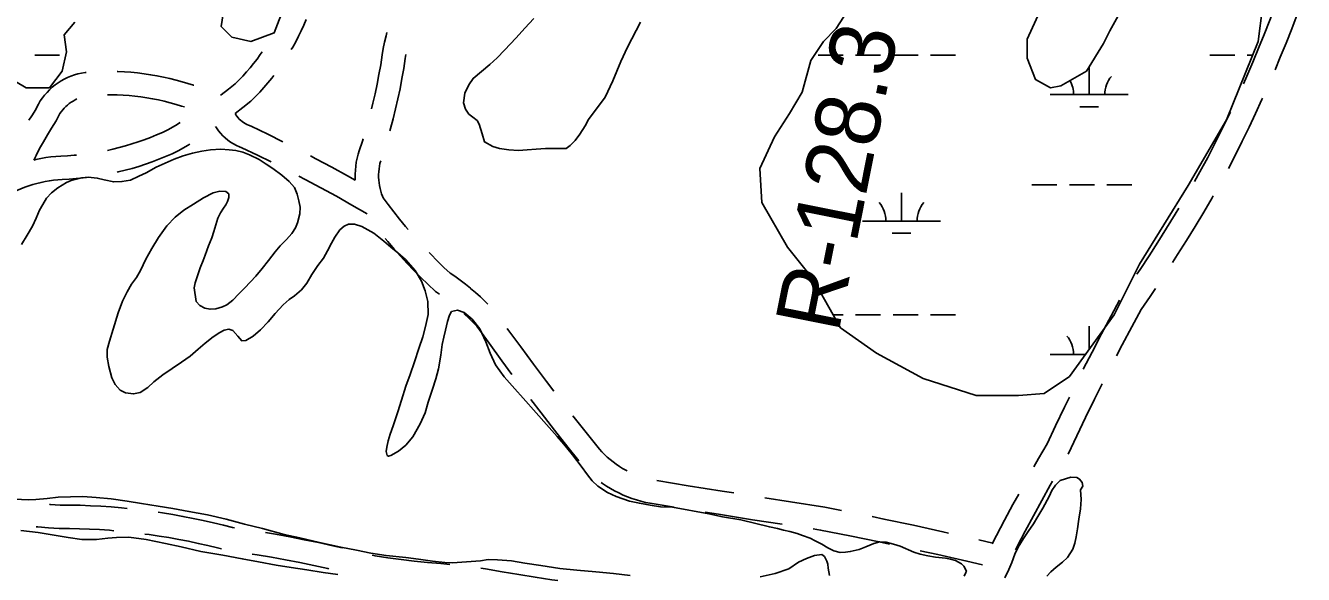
# Model space of a CAD drawing. Extents: x 3535183 to 3573198, y 534952 to 560562.
# Drawn here: x 3560733 to 3562370, y 548151 to 548854 of the extents above; entities that cross this region are included whole.
import ezdxf

# ---------------------------------------------------------------- set-up
doc = ezdxf.new("R2010")
doc.units = 0
for name, color, linetype in [('V-RIVR-RANG-IDEN', 7, 'Continuous'), ('V-ROAD-CNTR', 7, 'Continuous'), ('V-TOPO-SHOR', 7, 'Continuous'), ('V-WETL-SWMP', 7, 'Continuous')]:
    doc.layers.add(name, color=color, linetype=linetype)

msp = doc.modelspace()

# ---------------------------------------------------------------- linework, layer by layer
at = {"layer": 'V-ROAD-CNTR'}
msp.add_line((3561954.5, 548194.8), (3561972.4, 548190.7), dxfattribs=at)
for points in [[(3562370.2, 548890.2), (3562369.2, 548886.7), (3562362.2, 548867.9), (3562355.2, 548849.5), (3562348, 548831.2), (3562340.6, 548813), (3562333.9, 548797.1)], [(3561092.4, 548861.5), (3561089.4, 548854.3), (3561086.1, 548847.1), (3561082.7, 548839.9), (3561079, 548832.9), (3561075.2, 548825.9), (3561073.4, 548822.8)], [(3562331.5, 548871.6), (3562327.2, 548860.4), (3562320.1, 548842.4), (3562312.8, 548824.5), (3562305.3, 548806.7), (3562297.7, 548788.9), (3562293.3, 548779.2)], [(3561196, 548844.9), (3561194.8, 548840.5), (3561192.9, 548832.4), (3561191.3, 548824.3), (3561189.8, 548816.2), (3561187.9, 548803.5), (3561185.7, 548791), (3561183.4, 548778.7), (3561180.8, 548766.3), (3561177.9, 548754.1), (3561176.2, 548746.9)], [(3561036, 548819.8), (3561033.7, 548816.6), (3561029.5, 548810.8), (3561025.1, 548805.1), (3561020.6, 548799.6), (3561015.9, 548794.2), (3561011.1, 548788.9), (3561006.2, 548783.8), (3561001.5, 548779.2), (3560992.8, 548772.3), (3560983.5, 548765.1), (3560982.7, 548764.5)], [(3561220.3, 548816.4), (3561219.4, 548811.3), (3561217.5, 548798.6), (3561215.2, 548785.7), (3561212.8, 548772.8), (3561210.1, 548759.9), (3561207.1, 548747.1), (3561204, 548734.3), (3561200.6, 548721.6), (3561199.7, 548718.6)], [(3560810.4, 548793.5), (3560809.2, 548793.4), (3560804.5, 548792.6), (3560800, 548791.6), (3560795.5, 548790.4), (3560791.1, 548788.9), (3560786.7, 548787.1), (3560782.5, 548785), (3560778.5, 548782.8), (3560774.5, 548780.3), (3560770.7, 548777.6), (3560767.1, 548774.6), (3560763.6, 548771.5), (3560760.4, 548768.1), (3560757.3, 548764.6), (3560754.4, 548760.9), (3560751.8, 548757.1), (3560749.4, 548753.1), (3560747.2, 548749), (3560745.9, 548746.1), (3560740.8, 548738.1), (3560737.3, 548732.4)], [(3560948.5, 548777.1), (3560948, 548777.3), (3560940.7, 548779.5), (3560933.7, 548781.4), (3560925.9, 548783.6), (3560917.8, 548785.7), (3560909.6, 548787.6), (3560901.3, 548789.3), (3560893, 548790.7), (3560884.7, 548792), (3560876.4, 548793), (3560868, 548793.8), (3560859.6, 548794.4), (3560851.2, 548794.8), (3560850.4, 548794.8)], [(3561051.1, 548789.7), (3561048.6, 548786.4), (3561043.5, 548780.3), (3561038.4, 548774.3), (3561033, 548768.4), (3561027.5, 548762.7), (3561021.4, 548756.7), (3561011.3, 548748.6), (3561001.6, 548741.2), (3561001.3, 548740.9)], [(3560936.5, 548749.4), (3560932.5, 548750.6), (3560925.7, 548752.5), (3560918, 548754.6), (3560910.6, 548756.6), (3560903.2, 548758.3), (3560895.7, 548759.8), (3560888.2, 548761.1), (3560880.7, 548762.2), (3560873.1, 548763.2), (3560865.5, 548763.9), (3560857.9, 548764.4), (3560850.3, 548764.8), (3560842.7, 548764.9), (3560838.1, 548764.9)], [(3562317.8, 548760.5), (3562317.1, 548758.9), (3562308.9, 548741), (3562300.5, 548723.3), (3562291.9, 548705.6), (3562283.1, 548688), (3562274.1, 548670.5)], [(3560798.8, 548759.6), (3560796.3, 548758.4), (3560793.8, 548757), (3560791.3, 548755.4), (3560788.9, 548753.7), (3560786.6, 548751.8), (3560784.5, 548749.9), (3560782.4, 548747.8), (3560780.5, 548745.6), (3560778.7, 548743.3), (3560777, 548740.8), (3560775.5, 548738.3), (3560774.1, 548735.7), (3560772.3, 548731.7), (3560766.2, 548722.2), (3560760.9, 548713.6), (3560755.8, 548704.9), (3560750.9, 548696.1), (3560746.3, 548687.2), (3560743.4, 548681.4)], [(3560930.8, 548729.3), (3560925, 548725.8), (3560915.4, 548720.1), (3560908.3, 548716.8), (3560900.6, 548713.5), (3560892.8, 548710.3), (3560885, 548707.3), (3560877.1, 548704.6), (3560869.1, 548702), (3560861.1, 548699.6), (3560853, 548697.4), (3560844.8, 548695.4), (3560837.8, 548693.8)], [(3561062.6, 548704.9), (3561043.2, 548714.5), (3561021.8, 548724.8), (3561018.5, 548726.1), (3561016.4, 548727), (3561014.3, 548728.2), (3561012.3, 548729.4), (3561010.4, 548730.8), (3561008.5, 548732.3), (3561006.8, 548733.9), (3561005.2, 548735.6), (3561003.7, 548737.4), (3561002.3, 548739.3), (3561001.3, 548740.9)], [(3562276.6, 548742.9), (3562273.4, 548736.2), (3562265, 548718.8), (3562256.4, 548701.6), (3562247.6, 548684.5), (3562237.5, 548666.3), (3562230.6, 548654.1)], [(3561047.6, 548678.9), (3561030, 548687.6), (3561010, 548697.2), (3561007, 548698.4), (3561003.1, 548700.1), (3560999.3, 548702.2), (3560995.6, 548704.4), (3560992.1, 548706.9), (3560988.8, 548709.7), (3560985.7, 548712.6), (3560982.7, 548715.7), (3560980, 548719), (3560977.4, 548722.5), (3560976.2, 548724.4)], [(3560943.3, 548701.7), (3560940.4, 548700), (3560929.3, 548693.5), (3560920.6, 548689.4), (3560912.2, 548685.8), (3560903.8, 548682.4), (3560895.3, 548679.2), (3560886.7, 548676.1), (3560878, 548673.3), (3560869.3, 548670.7), (3560860.5, 548668.3), (3560851.7, 548666.2), (3560850.4, 548665.9)], [(3561165.4, 548708.4), (3561164.5, 548705.5), (3561160.5, 548693.3), (3561159, 548688.7), (3561157.8, 548683.8), (3561156.7, 548678.7), (3561156, 548673.7), (3561155.5, 548668.6), (3561155.2, 548663.5), (3561155.2, 548658.4), (3561155.4, 548655.6)], [(3560798.3, 548687.8), (3560795.2, 548687.5), (3560786.8, 548686.8), (3560778.2, 548686.4), (3560771.8, 548686), (3560765.4, 548685.4), (3560759, 548684.5), (3560752.6, 548683.4), (3560746.2, 548682.1), (3560743.4, 548681.4)], [(3561155.4, 548655.6), (3561145.6, 548661.1), (3561125.4, 548672.2), (3561105, 548683.1), (3561098.2, 548686.7)], [(3561187.9, 548680.4), (3561187, 548677), (3561186.3, 548673.5), (3561185.8, 548670), (3561185.4, 548666.4), (3561185.2, 548662.8), (3561185.2, 548659.3), (3561185.4, 548655.7), (3561185.8, 548652.1), (3561186.4, 548648.6), (3561187.1, 548645.1), (3561188, 548641.6), (3561189.1, 548638.2), (3561190.4, 548634.9), (3561191.3, 548632.8), (3561197.5, 548624.4), (3561204.8, 548614.9), (3561212.2, 548605.5), (3561219.8, 548596.3), (3561223.1, 548592.5)], [(3560811, 548659), (3560806.8, 548658.5), (3560797.8, 548657.6), (3560788.7, 548656.9), (3560779.9, 548656.5), (3560774.3, 548656.1), (3560768.9, 548655.6), (3560763.5, 548654.8), (3560758.1, 548653.9), (3560752.8, 548652.8), (3560747.5, 548651.5), (3560742.2, 548650.1), (3560737, 548648.4), (3560731.9, 548646.6), (3560726.8, 548644.7), (3560721.8, 548642.5), (3560716.8, 548640.2), (3560714, 548638.7)], [(3561170.7, 548612.3), (3561150.9, 548623.7), (3561131.1, 548634.9), (3561111.1, 548645.8), (3561091, 548656.6), (3561083.2, 548660.6)], [(3562254.6, 548635.6), (3562253.1, 548633.1), (3562242.4, 548614.7), (3562231.5, 548596.4), (3562220.3, 548578.2), (3562209, 548560.2), (3562202.6, 548550.2)], [(3562210.4, 548619.6), (3562205.8, 548611.9), (3562194.8, 548594), (3562183.7, 548576.2), (3562172.4, 548558.5), (3562160.8, 548541), (3562156.9, 548535.1)], [(3561193.6, 548581), (3561196.9, 548577), (3561205, 548567.4), (3561213.3, 548558.1), (3561221.8, 548548.9), (3561230.5, 548539.8), (3561239.3, 548530.9), (3561248.3, 548522.2), (3561258.2, 548512.9), (3561263.2, 548509.5)], [(3561249.9, 548562.9), (3561252, 548560.7), (3561260.4, 548552.2), (3561269, 548543.9), (3561277, 548536.4), (3561282.8, 548532.5), (3561289.7, 548527.6), (3561296.4, 548522.5), (3561302.9, 548517.3)], [(3561303.2, 548517), (3561309.5, 548511.7), (3561315.8, 548506.1), (3561321.9, 548500.3), (3561325.3, 548496.9)], [(3562180.7, 548516.8), (3562173.9, 548506.7), (3562162.4, 548489.9), (3562150.3, 548467.6), (3562138, 548444.6), (3562130.6, 548430.4)], [(3562134.7, 548501.8), (3562123.9, 548481.8), (3562111.5, 548458.6), (3562099.3, 548435.3), (3562088.1, 548413.4)], [(3561294.3, 548485), (3561295.4, 548484), (3561301, 548478.8), (3561306.4, 548473.4), (3561311.1, 548468.4), (3561326.7, 548446.7), (3561343.2, 548424.2), (3561356.1, 548406.8)], [(3561350.1, 548465.6), (3561351, 548464.3), (3561367.3, 548442), (3561383.8, 548419.8), (3561400.4, 548397.8), (3561409.9, 548385.4)], [(3562112.4, 548394.8), (3562102.5, 548375.1), (3562091.1, 548351.7), (3562079.9, 548328.2), (3562068.9, 548304.7)], [(3561380.2, 548374.8), (3561393.4, 548357.5), (3561410.5, 548335.5), (3561427.8, 548313.7), (3561441.8, 548296.1)], [(3562070.3, 548377.5), (3562064.1, 548364.8), (3562052.7, 548341), (3562041.9, 548317.9), (3562030.9, 548299.1), (3562024.9, 548288.5)], [(3561434.3, 548353.8), (3561451.3, 548332.3), (3561468.3, 548311.1), (3561471.4, 548307.6), (3561474.8, 548304.1), (3561478.3, 548300.8), (3561482, 548297.6), (3561485.8, 548294.6), (3561489.7, 548291.7), (3561493.7, 548289), (3561497.8, 548286.4), (3561502, 548284), (3561503.8, 548283.1)], [(3561541.6, 548270.7), (3561581.9, 548264.2), (3561625.5, 548257.2), (3561640.3, 548254.9)], [(3562048.9, 548270), (3562045.9, 548264.8), (3562035, 548245.4), (3562024.3, 548225.8), (3562013.8, 548206.2), (3562003.5, 548186.5), (3562001.2, 548182.1)], [(3561470.6, 548268.5), (3561472.3, 548267.2), (3561477.3, 548263.8), (3561482.5, 548260.6), (3561487.7, 548257.6), (3561493.1, 548254.9), (3561498.6, 548252.3), (3561504.1, 548250), (3561509.8, 548247.9), (3561515.5, 548246), (3561521.4, 548244.3), (3561527.2, 548242.9), (3561533.1, 548241.7), (3561564.1, 548236.7)], [(3562005.4, 548253.6), (3561998, 548240.1), (3561987.3, 548220.3), (3561976.9, 548200.3), (3561971.4, 548189.8)], [(3560763.4, 548240.4), (3560764.4, 548240.3), (3560777.1, 548239.5), (3560789.8, 548239.4), (3560803, 548239.1), (3560816.3, 548238.6), (3560829.5, 548237.9), (3560842.7, 548237), (3560855.9, 548235.9), (3560863.2, 548235.2)], [(3561679.9, 548248.7), (3561712.8, 548243.6), (3561756.8, 548236.9), (3561778.5, 548232.6)], [(3560902.9, 548230.2), (3560908.5, 548229.4), (3560921.6, 548227.3), (3560934.6, 548224.9), (3560947.6, 548222.4), (3560960.6, 548219.6), (3560973.5, 548216.7), (3560986.4, 548213.6), (3560998.2, 548210.5), (3561000.8, 548210.1)], [(3561603.6, 548230.3), (3561620.8, 548227.6), (3561664.5, 548220.7), (3561702.4, 548214.8)], [(3561817.7, 548224.6), (3561832.7, 548221.5), (3561870.5, 548213.5), (3561908.2, 548205.3), (3561915.5, 548203.6)], [(3560746.3, 548211.7), (3560748.6, 548211.5), (3560762.1, 548210.4), (3560776, 548209.5), (3560789.3, 548209.4), (3560802.1, 548209.1), (3560814.9, 548208.6), (3560827.7, 548208), (3560840.4, 548207.1), (3560846.1, 548206.6)], [(3561040.3, 548204.1), (3561053.1, 548202), (3561071.6, 548198.7), (3561090, 548195.1), (3561108.4, 548191.4), (3561126.8, 548187.4), (3561138.4, 548184.7)], [(3561742, 548208.8), (3561751.6, 548207.4), (3561789, 548199.9), (3561826.6, 548192.2), (3561840, 548189.3)], [(3560885.9, 548202.3), (3560891.2, 548201.6), (3560903.9, 548199.7), (3560916.5, 548197.7), (3560929.1, 548195.4), (3560941.6, 548193), (3560954.1, 548190.3), (3560966.6, 548187.5), (3560979, 548184.5), (3560984, 548183.2)], [(3561023.4, 548176.5), (3561029.8, 548175.5), (3561047.9, 548172.5), (3561066.1, 548169.2), (3561084.2, 548165.7), (3561102.2, 548162), (3561120.2, 548158.1), (3561121.6, 548157.8)], [(3561177.2, 548175.1), (3561180.7, 548174.2), (3561197, 548171.9), (3561214, 548169.7), (3561231, 548167.7), (3561248, 548165.9), (3561265.1, 548164.4), (3561276.5, 548163.5)], [(3561879.1, 548180.9), (3561901.7, 548176), (3561939.1, 548167.6), (3561958.9, 548163)], [(3561316.2, 548158.8), (3561322.4, 548157.6), (3561343.6, 548153.8), (3561364.8, 548150.3), (3561386, 548146.9), (3561407.3, 548143.7), (3561414.8, 548142.7)]]:
    msp.add_lwpolyline(points, dxfattribs=at)
at = {"layer": 'V-TOPO-SHOR'}
for points in [[(3561520.7, 548858.1), (3561504.3, 548826), (3561495.7, 548807.4), (3561485.2, 548783), (3561475.4, 548762.1), (3561454, 548733.5), (3561449.7, 548725), (3561443.1, 548714.6), (3561436.9, 548706.5), (3561430.7, 548699.9), (3561425.6, 548696), (3561420.2, 548696.1), (3561410.5, 548696.1), (3561399.3, 548696.1), (3561387.2, 548695.4), (3561375.6, 548694.3), (3561364.4, 548693.5), (3561352, 548694.4), (3561340, 548696.3), (3561331.8, 548698.7), (3561321, 548704.5), (3561318, 548715), (3561314.1, 548727.4), (3561311.4, 548732.1), (3561306, 548736.4), (3561301, 548740.3), (3561296.7, 548746.5), (3561294.1, 548754.6), (3561295.7, 548767), (3561300.7, 548777.8), (3561306.2, 548786), (3561317.1, 548794.8), (3561327.6, 548803.7), (3561337.3, 548812.2), (3561346.6, 548822.2), (3561361.4, 548838.1), (3561372.7, 548850.4), (3561384.3, 548862.8)], [(3560946.8, 548690.3), (3560958.9, 548692.9), (3560969.9, 548694.4), (3560983, 548695.4), (3560993.8, 548694.6), (3561002.4, 548693.6), (3561011.4, 548691.3), (3561019.7, 548688.2), (3561032.2, 548681.9), (3561041, 548676.2), (3561049.8, 548670.5), (3561061.3, 548662.2), (3561070.5, 548654), (3561077.5, 548646), (3561081, 548637.8), (3561083.1, 548629.2), (3561084.6, 548621), (3561084.4, 548612.5), (3561081.5, 548601), (3561078.7, 548594.6), (3561074.1, 548587.2), (3561067.4, 548579.4), (3561059.3, 548571.3), (3561052.7, 548563.6), (3561044.2, 548552.7), (3561036.2, 548542.5), (3561027.9, 548532.8), (3561021.3, 548525.5), (3561013.3, 548517.3), (3561006.2, 548509.8), (3560998.6, 548502), (3560990.6, 548496), (3560985.3, 548493.5), (3560976.8, 548490.7), (3560969.4, 548490.3), (3560962.5, 548491.7), (3560956.4, 548494.9), (3560951.7, 548500.3), (3560948.8, 548517.8), (3560950.2, 548524.1), (3560953.9, 548535.7), (3560956.6, 548543.2), (3560960.3, 548552.7), (3560963.1, 548559.7), (3560967.5, 548571.3), (3560971.4, 548581.6), (3560974, 548589.7), (3560976.5, 548598.4), (3560979.4, 548607), (3560982.7, 548613.7), (3560986.5, 548619.8), (3560989.5, 548624.1), (3560991.5, 548628.1), (3560993.5, 548633.3), (3560993.2, 548638.1), (3560989.4, 548641.1), (3560982, 548641.5), (3560973.3, 548639.3), (3560961, 548633), (3560948, 548625), (3560935.5, 548617.3), (3560924.6, 548608.3), (3560913.8, 548597), (3560903.1, 548582.1), (3560894.6, 548567.9), (3560887, 548554.6), (3560880.1, 548539.9), (3560874.9, 548530.9), (3560868.6, 548522.2), (3560863.2, 548512.7), (3560857.1, 548500.8), (3560851.6, 548485.5), (3560845.2, 548464.7), (3560840.4, 548449.5), (3560837.3, 548438.8), (3560837.3, 548429), (3560839.4, 548417.1), (3560843.5, 548402.6), (3560847.6, 548394), (3560854, 548386.5), (3560861, 548383.1), (3560871.3, 548381.9), (3560879.6, 548383.7), (3560889.7, 548389.9), (3560897.2, 548397.2), (3560908.6, 548406.1), (3560932.9, 548422.6), (3560943.6, 548430.3), (3560954.2, 548439.3), (3560963.1, 548447), (3560973.1, 548454.9), (3560981.9, 548460.5), (3560987.4, 548463.3), (3560993.4, 548464.6), (3560998.6, 548463.1)], [(3560867.2, 548655.6), (3560878.1, 548660.7), (3560887.4, 548665.2), (3560900.3, 548672.4), (3560923.5, 548682.4), (3560935, 548686.7), (3560946.8, 548690.3)], [(3560727.5, 548573.4), (3560734.9, 548585.3), (3560741.7, 548596.8), (3560746.4, 548607), (3560750.8, 548617.1), (3560754.9, 548624.6), (3560759.9, 548632.4), (3560766.2, 548639.3), (3560774.3, 548645.8), (3560785.2, 548652.5), (3560791.5, 548655.1), (3560798.1, 548656.9), (3560805, 548658.6), (3560813.1, 548659.5), (3560824.7, 548658.2), (3560833.6, 548656.2), (3560846, 548653.4), (3560856.4, 548653.7), (3560867.2, 548655.6)], [(3561043.7, 548474.1), (3561052.9, 548485), (3561063, 548496.1), (3561070.7, 548502.8), (3561077.6, 548507.6), (3561086.4, 548515), (3561093.5, 548523.7), (3561099.9, 548534.6), (3561107.2, 548546.1), (3561114.6, 548555.8), (3561119.8, 548564.9), (3561124.9, 548574.8), (3561129.2, 548582.7), (3561135.4, 548591.8), (3561141, 548596.8), (3561146.6, 548599.1), (3561154.2, 548599.4), (3561163.7, 548596.3), (3561179, 548587.9), (3561192, 548577.5), (3561200.8, 548569.6), (3561209.7, 548562.4), (3561219.5, 548554.1), (3561232.2, 548540.1), (3561240.1, 548526.3), (3561245.1, 548513.7), (3561248.3, 548500.1), (3561248.7, 548483.7), (3561245.5, 548468.2), (3561242, 548454.9), (3561237, 548439.8), (3561231.1, 548422.9), (3561225.7, 548406.7), (3561220.3, 548391.7), (3561214.4, 548374), (3561209.8, 548359), (3561203.9, 548341.1), (3561200.2, 548330.2), (3561197.7, 548321.9), (3561195.7, 548313.7), (3561195.1, 548308.2), (3561196.4, 548303.1), (3561198, 548302), (3561200.9, 548303.1), (3561210.7, 548308.3), (3561220.1, 548316), (3561229.3, 548327), (3561238.7, 548343.4), (3561244.7, 548357.6), (3561248.9, 548371.2), (3561254.3, 548387.9), (3561258.6, 548401.2), (3561261.8, 548414.1), (3561264.9, 548431.4), (3561266.9, 548445.3), (3561268.9, 548454.7), (3561271.1, 548463.4), (3561273.6, 548474.4), (3561276.1, 548482.5), (3561278.7, 548487.3), (3561286.5, 548489.1), (3561294.9, 548486.1), (3561305, 548477.7), (3561315.1, 548465.2), (3561322.5, 548448.7), (3561328, 548434.1), (3561335, 548419.2), (3561346.1, 548403.7), (3561359.6, 548388.5), (3561370.6, 548376.3), (3561387.2, 548357.6), (3561400.5, 548342.8), (3561414.2, 548327.2), (3561422.4, 548317.3), (3561433.7, 548303.7), (3561445, 548289.2), (3561452.8, 548278.2), (3561459, 548270.5), (3561466.2, 548263.7), (3561478.6, 548255.7), (3561489.6, 548250.2), (3561506.6, 548244.3), (3561519.5, 548241.8), (3561533.2, 548239.5), (3561546.4, 548237.3), (3561562, 548236.8), (3561608.4, 548228.3), (3561625.9, 548224.3), (3561649.3, 548220.4), (3561685.9, 548211.5), (3561696.5, 548209.3), (3561704.1, 548207.3), (3561712.2, 548205.4), (3561721.4, 548202.8), (3561728.4, 548200.5)], [(3560998.6, 548463.1), (3561004.8, 548455.9), (3561009.9, 548450), (3561015.2, 548450.2), (3561024.7, 548455.6), (3561034.1, 548463.7), (3561043.7, 548474.1)], [(3561987.8, 548146.2), (3561992.6, 548157), (3561996.4, 548166), (3562000.4, 548176.4), (3562004.9, 548185.6), (3562011.4, 548196.8), (3562017.7, 548205.6), (3562024.3, 548215.3), (3562030, 548224.8), (3562036.5, 548235.5), (3562044.5, 548250.6), (3562047.9, 548257.9), (3562052.7, 548265), (3562058.5, 548270.9), (3562072.2, 548275.3), (3562080, 548274.7), (3562083.3, 548272.8), (3562086.7, 548268.4), (3562087.7, 548263.8), (3562084.7, 548258.9)], [(3562084.7, 548258.9), (3562085.5, 548246.5), (3562084.6, 548234.5), (3562082.5, 548221.2), (3562080.7, 548209), (3562079.1, 548198.8), (3562077.2, 548190.6), (3562074.6, 548182.8), (3562067.7, 548172.2), (3562061.5, 548166.1), (3562053.4, 548159.9), (3562046.6, 548153.9), (3562041.6, 548148.4)], [(3561315.6, 548168), (3561280.1, 548165.5), (3561270.1, 548165.9), (3561254.5, 548167.5), (3561236.4, 548170), (3561220, 548172.2), (3561194.8, 548175), (3561175.5, 548178), (3561156.8, 548181.7), (3561137, 548185.5), (3561109.6, 548191.4), (3561084.5, 548197.3), (3561064.2, 548201.8), (3561036.6, 548209.3), (3561013.5, 548214.9), (3560989.8, 548221.4), (3560965.9, 548226.8), (3560942.2, 548231.3), (3560921.5, 548235.2), (3560902.8, 548238.2), (3560881.6, 548241.6), (3560863.2, 548244.6), (3560842.7, 548247.6), (3560823.5, 548249.2), (3560806.2, 548250.2), (3560774.6, 548249.7), (3560760.4, 548247.9), (3560746, 548246.4), (3560736.6, 548246.3), (3560718.6, 548246.9)], [(3560726.9, 548206.9), (3560749.1, 548204.1), (3560769.7, 548200.7), (3560787.5, 548197.8), (3560804.8, 548195.5), (3560823.8, 548195.3), (3560838.5, 548197.1), (3560849.5, 548198.1), (3560865.2, 548198.5), (3560887.4, 548195.4), (3560912.3, 548190.2), (3560932.1, 548185.9), (3560957.5, 548180), (3560985.8, 548175.1), (3561010.6, 548170.6), (3561031.4, 548166.7), (3561053.9, 548162.5), (3561073.2, 548159.3), (3561093.1, 548156.5), (3561114.3, 548153.1), (3561132.9, 548150.6)], [(3561728.4, 548200.5), (3561738.1, 548196.9), (3561744.8, 548193.8), (3561753.1, 548189.5), (3561760.9, 548184.8), (3561768.4, 548180.9), (3561776.8, 548178.7)], [(3561776.8, 548178.7), (3561783.5, 548179.2), (3561789.5, 548179.9), (3561801, 548182.5), (3561809.6, 548185.8), (3561819.6, 548190.1), (3561827.5, 548192.3), (3561835.5, 548191.9), (3561845, 548189.2), (3561853.4, 548186.6), (3561871.1, 548179.3), (3561879, 548176.5), (3561889.1, 548174.5), (3561898.9, 548172.6), (3561911.4, 548171.4), (3561918, 548170.1), (3561924.4, 548168.3), (3561932.1, 548164.3), (3561935.1, 548161.2), (3561938.3, 548154.9), (3561937.7, 548152.9), (3561935.4, 548148.2)], [(3561763, 548149.1), (3561761.2, 548158.4), (3561760.9, 548163.9), (3561759.7, 548167.6), (3561756.5, 548173.7), (3561753, 548176.2), (3561743.7, 548175), (3561733.7, 548170.9), (3561723.4, 548166.2), (3561710.8, 548157.8), (3561693.2, 548151.7), (3561674.2, 548147.5)], [(3561507.5, 548149.3), (3561486.4, 548151.7), (3561463.7, 548154), (3561439.1, 548156.1), (3561417.3, 548158.2), (3561393.3, 548161.9), (3561372.6, 548165.2), (3561355.4, 548168), (3561337.8, 548169.3), (3561325.6, 548169.5), (3561315.6, 548168)]]:
    msp.add_lwpolyline(points, dxfattribs=at)
at = {"layer": 'V-WETL-SWMP'}
for p, q in [((3560744.6, 548815.9), (3560776.6, 548815.9)), ((3561748.4, 548815.9), (3561780.4, 548815.9)), ((3561796.4, 548815.9), (3561828.4, 548815.9)), ((3561844.4, 548815.9), (3561876.4, 548815.9)), ((3561892.4, 548815.9), (3561924.4, 548815.9)), ((3562250.3, 548815.9), (3562282.3, 548815.9)), ((3562298.3, 548815.9), (3562305.1, 548815.9)), ((3562095.7, 548765.2), (3562095.7, 548801.2)), ((3562045.7, 548765.2), (3562145.7, 548765.2)), ((3562083.7, 548749.7), (3562107.7, 548749.7)), ((3562022.3, 548649.7), (3562054.3, 548649.7)), ((3562070.3, 548649.7), (3562102.3, 548649.7)), ((3562118.3, 548649.7), (3562150.3, 548649.7)), ((3561855.2, 548603.3), (3561855.2, 548639.3)), ((3561805.2, 548603.3), (3561905.2, 548603.3)), ((3561843.2, 548587.9), (3561867.2, 548587.9)), ((3561767.6, 548483.2), (3561780.4, 548483.2)), ((3561796.4, 548483.2), (3561828.4, 548483.2)), ((3561844.4, 548483.2), (3561876.4, 548483.2)), ((3561892.4, 548483.2), (3561924.4, 548483.2)), ((3562095.7, 548439.1), (3562095.7, 548468.5)), ((3562045.7, 548432.5), (3562090.9, 548432.5))]:
    msp.add_line(p, q, dxfattribs=at)
for points in [[(3562317.7, 548876.9), (3562312.2, 548833.4), (3562271.5, 548732.9), (3562222.6, 548648.7), (3562160.1, 548548.2), (3562127.5, 548482.9), (3562070.4, 548404.1), (3562037.8, 548382.4), (3562005.2, 548379.7), (3561950.9, 548379.7), (3561882.9, 548401.4), (3561823.1, 548434), (3561777, 548466.6), (3561741.6, 548529.1), (3561709, 548569.9), (3561676.4, 548626.9), (3561673.7, 548670.4), (3561692.7, 548711.2), (3561711.7, 548741.1), (3561728.1, 548768.2), (3561738.9, 548809), (3561755.2, 548833.4), (3561771.5, 548849.8), (3561825.9, 548934)], [(3561065.1, 548879.6), (3561051.5, 548844.3), (3561021.6, 548833.4), (3560997.2, 548838.9), (3560983.6, 548852.5), (3560986.3, 548868.8)], [(3562032.4, 548871.5), (3562016.1, 548836.2), (3562016.1, 548811.7), (3562026.9, 548784.5), (3562046, 548773.7), (3562059.5, 548776.4), (3562092.1, 548795.4), (3562113.9, 548830.7), (3562122, 548847), (3562132.9, 548866.1)], [(3560796.1, 548857.9), (3560782.5, 548841.6), (3560785.2, 548819.9), (3560779.8, 548795.4), (3560763.5, 548773.7), (3560733.6, 548773.7), (3560706.4, 548790)]]:
    msp.add_lwpolyline(points, dxfattribs=at)
for centre, start, end in [((3562040.5, 548765.6), 359.2282, 29.7515), ((3562151, 548765.6), 139.2282, 180.7718), ((3561800, 548603.8), 359.2282, 40.7718), ((3561910.5, 548603.8), 139.2282, 180.7718), ((3562040.5, 548433), 359.2282, 40.7718)]:
    msp.add_arc(centre, 35.2, start, end, dxfattribs=at)

# ---------------------------------------------------------------- texts
at = {"layer": 'V-RIVR-RANG-IDEN'}
msp.add_text('R-128.3', height=83, rotation=78.732, dxfattribs=at).set_placement((3561774.3, 548458.4))

doc.saveas('drawing.dxf')
